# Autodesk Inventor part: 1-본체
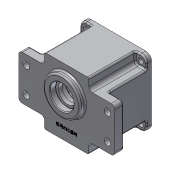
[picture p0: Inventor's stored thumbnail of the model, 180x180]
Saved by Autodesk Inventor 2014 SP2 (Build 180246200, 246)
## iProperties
Created: 2014-12
Part Number: 1-본체
Material: 알루미늄 6061
Document SubType Name: Modeling
Designer: 02
Density: 2.71 g/cm^3
Appearance: 알루미늄 - 평지
Mass: 705.361 g
Surface Area: 672.962 cm^2
Volume: 260.281 cm^3
Author: 02
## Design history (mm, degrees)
sketch "스케치1"
  geometry: L1 (-45, 45)-(45, 45); L2 (45, 45)-(45, -45); L3 (45, -45)-(-45, -45); L4 (-45, -45)-(-45, 45); 3 further points
  constraints: 8 end point, 2 midpoint, 2 parallel, 2 perpendicular, 1 horizontal, 1 horizontal alignment, 1 vertical alignment
  dimensions: "d0" = 90 distance of L1.start L1.end
extrude "돌출1" new body sketch "스케치1" distance "d1" = 70; taper "d2" = 0 deg
sketch "스케치2"
  geometry: L1 (45, 45)-(30, 45); L2 (30, 45)-(30, 30); L3 (30, 30)-(45, 30); L4 (45, 30)-(45, 45); L5 (45, -45)-(30, -45); L6 (30, -45)-(30, -30); L7 (30, -30)-(45, -30); L8 (45, -30)-(45, -45); L9 (-45, -45)-(-30, -45); L10 (-30, -45)-(-30, -30); L11 (-30, -30)-(-45, -30); L12 (-45, -30)-(-45, -45); L13 (-45, 45)-(-30, 45); L14 (-30, 45)-(-30, 30); L15 (-30, 30)-(-45, 30); L16 (-45, 30)-(-45, 45); L17 (-30, 30)-(30, 30); L18 (30, 30)-(30, -30); L19 (30, -30)-(-30, -30); L20 (-30, -30)-(-30, 30); 3 further points
  constraints: 40 end point, 10 parallel, 5 horizontal, 5 perpendicular, 2 midpoint, 1 horizontal alignment, 1 vertical alignment
  dimensions: "d3" = 60 distance between parallel lines of L7 L3; "d4" = 60 distance between parallel lines of L2 L14
extrude "돌출2" cut sketch "스케치2" distance "d5" = 63; taper "d6" = 0 deg
sketch "스케치3"
  geometry: L1 (-65, 30)-(65, 30); L2 (65, 30)-(65, -30); L3 (65, -30)-(-65, -30); L4 (-65, -30)-(-65, 30); 3 further points
  constraints: 8 end point, 2 midpoint, 2 parallel, 1 horizontal, 1 horizontal alignment, 1 perpendicular, 1 vertical alignment
  dimensions: "d7" = 60 distance of L1.end L2.end; "d8" = 130 distance of L1.start L1.end
extrude "돌출3" join sketch "스케치3" distance "d9" = 12; taper "d10" = 0 deg
fillet "모깎기1" dims "d12" = 8
sketch "스케치5"
  geometry: A1 r 8 centre (37, 37) between (45, 37) and (37, 45) reference; A2 r 8 centre (37, -37) between (37, -45) and (45, -37) reference; A3 r 8 centre (-37, -37) between (-45, -37) and (-37, -45) reference; A4 r 8 centre (-37, 37) between (-37, 45) and (-45, 37) reference; 1 further point
hole "구멍1" sketch "스케치5" at (37, 37), (-37, 37), (-37, -37), (37, -37) diameter "d13" = 7; stored, may be unused: countersink angle "d17" = 90 deg, drill point angle "d19" = 118 deg; dims "d14" = 6, "d15" = 4, "d16" = 2, "d18" = 8
sketch "스케치6"
  geometry: L1 (-55, 17.5)-(55, 17.5); L2 (55, 17.5)-(55, -17.5); L3 (55, -17.5)-(-55, -17.5); L4 (-55, -17.5)-(-55, 17.5); 3 further points
  constraints: 8 end point, 2 midpoint, 2 parallel, 1 horizontal, 1 horizontal alignment, 1 perpendicular, 1 vertical alignment
  dimensions: "d20" = 110 distance of L1.start L1.end; "d21" = 35 distance of L1.end L2.end
hole "구멍2" sketch "스케치6" at (55, 17.5), (55, -17.5), (-55, -17.5), (-55, 17.5) diameter "d22" = 9; stored, may be unused: countersink angle "d26" = 90 deg, drill point angle "d28" = 118 deg; dims "d23" = 6, "d24" = 4, "d25" = 2, "d27" = 8
sketch "스케치7"
  geometry: C1 r 39 at (0, 0); 1 further point
  constraints: 1 centre point, 1 coincident
  dimensions: "d29" = 78 diameter of C1
extrude "돌출4" cut sketch "스케치7" distance "d30" = 61; taper "d31" = 0 deg
sketch "스케치8"
  geometry: C1 r 39 at (0, 0) reference; C2 r 40 at (0, 0)
  constraints: 1 centre point, 1 coincident
  dimensions: "d32" = 80 diameter of C2
extrude "돌출5" cut sketch "스케치8" distance "d33" = 9; taper "d34" = 0 deg
sketch "스케치9"
  geometry: L1 (0, 0)-(0, 11); L2 (0, 0)-(0, -20); C1 r 39 at (0, 0) reference; A1 r 20.5 centre (0, 11) between (7.402, -8.117) and (-7.402, -8.117); A2 r 14 centre (0, -20) between (-7.402, -8.117) and (7.402, -8.117); A3 r 14 centre (0, -20) between (0, -6) and (-7.402, -8.117); A4 r 14 centre (0, -20) between (7.402, -8.117) and (0, -6); A5 r 20.5 centre (0, 11) between (0, -9.5) and (7.402, -8.117); A6 r 20.5 centre (0, 11) between (-7.402, -8.117) and (0, -9.5)
  constraints: 12 point on circle, 6 centre point, 4 end point, 2 coincident, 2 point on line, 1 collinear, 1 vertical
  dimensions: "d35" = 11 distance of L1.start L1.end; "d36" = 20 distance of L1.start L2.end; "d37" = 14 radius of A2; "d38" = 20.5 radius of A1
extrude "돌출6" join sketch "스케치9" distance "d39" = 7; taper "d40" = 0 deg
sketch "스케치10"
  geometry: C1 r 25 at (0, 11); A1 r 20.5 centre (0, 11) between (7.402, -8.117) and (-7.402, -8.117) reference; 1 further point
  constraints: 1 centre point, 1 coincident
  dimensions: "d41" = 50 diameter of C1
extrude "돌출7" join sketch "스케치10" distance "d42" = 7; taper "d43" = 0 deg
sketch "스케치11"
  geometry: C1 r 25 at (0, 0) reference; C2 r 16 at (0, 0); 1 further point
  constraints: 1 centre point, 1 coincident
  dimensions: "d44" = 32 diameter of C2
extrude "돌출8" cut sketch "스케치11" distance "d45" = 8; taper "d46" = 0 deg
sketch "스케치12"
  geometry: C1 r 17.5 at (0, 11); A1 r 20.5 centre (0, 11) between (7.402, -8.117) and (-7.402, -8.117) reference; 1 further point
  constraints: 1 centre point, 1 coincident
  dimensions: "d47" = 35 diameter of C1
extrude "돌출9" cut sketch "스케치12" distance "d48" = 10; taper "d49" = 0 deg
sketch "스케치13"
  geometry: C1 r 17.5 at (0, 0) reference; C2 r 12.5 at (0, 0); 1 further point
  constraints: 1 centre point, 1 coincident
  dimensions: "d50" = 25 diameter of C2
extrude "돌출10" cut sketch "스케치13" stored distance "d51" = 10; taper "d52" = 0 deg
sketch "스케치14"
  geometry: C1 r 11 at (0, -20); A1 r 14 centre (0, -20) between (-7.402, -8.117) and (7.402, -8.117) reference; 1 further point
  constraints: 1 centre point, 1 coincident
  dimensions: "d53" = 22 diameter of C1
extrude "돌출11" cut sketch "스케치14" distance "d54" = 7; taper "d55" = 0 deg
sketch "스케치15"
  geometry: C1 r 11 at (0, 0) reference; C2 r 9.5 at (0, 0); 1 further point
  constraints: 1 centre point, 1 coincident
  dimensions: "d56" = 19 diameter of C2
extrude "돌출12" cut sketch "스케치15" distance "d57" = 1; taper "d58" = 0 deg
sketch "스케치16" dims "d59" = 35
  geometry: L1 (0, 0)-(0, 39); L2 (0, 0)-(27.577, 27.577); L3 (24.603, 30.26)-(21.92, 27.577); L4 (27.577, 21.92)-(30.26, 24.603); A1 r 39 centre (0, 0) between (0, 39) and (27.577, 27.577) reference; A2 r 4 centre (24.749, 24.749) between (21.92, 27.577) and (27.577, 21.92); 1 further point
  constraints: 8 end point, 6 point on circle, 2 coincident, 2 parallel, 2 tangent, 1 centre point, 1 point on line, 1 vertical, 3 other
  dimensions: "d60" = 45 deg angle of L2 L1; "d61" = 4 radius of A2
extrude "돌출13" join sketch "스케치16" stored distance "d62" = 1; taper "d63" = 0 deg
sketch "스케치17"
  geometry: A1 r 4 centre (24.749, 24.749) between (21.92, 27.577) and (27.577, 21.92) reference
hole "구멍3" sketch "스케치17" at (24.749, 24.749) diameter "d64" = 3.459; stored, may be unused: countersink angle "d68" = 90 deg, drill point angle "d70" = 118 deg; dims "d65" = 12, "d66" = 4, "d67" = 2, "d69" = 15
fillet "모깎기3" dims "d72" = 3.5
fillet "모깎기4" dims "d76" = 3
fillet "모깎기5" dims "d77" = 5
fillet "모깎기6" dims "d78" = 0.3
fillet "모깎기7" dims "d79" = 2
fillet "모깎기9" dims "d81" = 5
fillet "모깎기8" dims "d80" = 2
chamfer "모따기1" distance "d82" = 1; stored, may be unused: second distance "d83" = 2, angle "d84" = 45 deg
sketch "스케치18"
  geometry: L1 (-30, -45)-(30, -45) reference; 4 further points
  constraints: 1 vertical alignment, 1 other
  dimensions: "d85" = 15 distance from line of point (0, -30) L1
feature "엠보싱1" sketch "스케치18" dims "d0" = 90, "d3" = 60, "d4" = 60, "d86" = 0.5, "d87" = 0
node "솔리드1"
pattern_circular "원형 패턴1" dims "d74" = 360 deg
